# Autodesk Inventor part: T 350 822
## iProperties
Created: 2006-07
Part Number: T 350 822
Document SubType Name: Modeling
Designer: I.Baliuc
Material: 2.0060
Description: Stromband
Density: 8.94 g/cm^3
Author: T.Messerschmitt
Revision Number: 350822
Comments: Model: C - erstellt für Strombahn DC/Schalter
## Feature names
1. Trennen1
2. Bezeichnung2 [Tagging]
